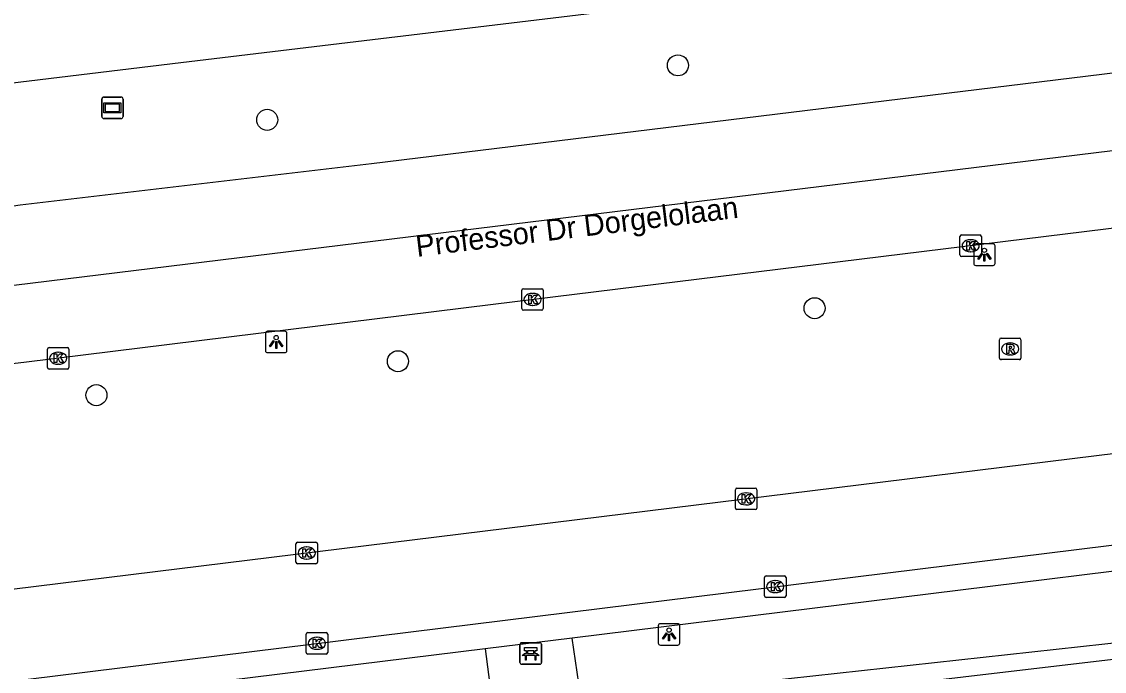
# Model space of a CAD drawing. Extents: x 161477 to 163040, y 383680 to 384868.
# Drawn here: x 162179.5 to 162229.8, y 384039.9 to 384070.2 of the extents above; entities that cross this region are included whole.
import ezdxf

# ---------------------------------------------------------------- set-up
doc = ezdxf.new("R2010")
doc.units = 0
for name, color, linetype in [('IMGEO_Bank', 7, 'Continuous'), ('IMGEO_Boom', 7, 'Continuous'), ('IMGEO_Haag', 7, 'Continuous'), ('IMGEO_Kolk', 7, 'Continuous'), ('IMGEO_Lichtpunt', 7, 'Continuous'), ('IMGEO_Openbare_ruimte_label', 7, 'Continuous'), ('IMGEO_Rijbaan_lokaal_gesloten', 7, 'Continuous'), ('IMGEO_Rioolput', 7, 'Continuous'), ('IMGEO_Verklikker', 7, 'Continuous'), ('IMGEO_Voetpad_open', 7, 'Continuous')]:
    doc.layers.add(name, color=color, linetype=linetype)

msp = doc.modelspace()

# ---------------------------------------------------------------- linework, layer by layer
at = {"layer": 'IMGEO_Bank'}
for p, q in [((162202.681, 384040.354), (162202.681, 384041.195)), ((162202.681, 384041.195), (162202.681, 384040.354)), ((162202.756, 384041.279), (162203.597, 384041.279)), ((162203.597, 384041.279), (162202.756, 384041.279)), ((162203.681, 384041.204), (162203.681, 384040.363)), ((162203.681, 384040.363), (162203.681, 384041.204)), ((162203.378, 384040.677), (162202.985, 384040.677)), ((162202.99, 384040.785), (162202.99, 384040.891)), ((162203.034, 384040.891), (162203.034, 384040.785)), ((162203.322, 384040.897), (162203.04, 384040.897)), ((162203.04, 384040.779), (162203.322, 384040.779)), ((162203.328, 384040.785), (162203.328, 384040.891)), ((162203.372, 384040.891), (162203.372, 384040.785)), ((162203.606, 384040.279), (162202.765, 384040.279)), ((162202.765, 384040.279), (162203.606, 384040.279))]:
    msp.add_line(p, q, dxfattribs=at)
for points in [[(162202.984, 384040.897), (162202.898, 384040.897), (162202.898, 384041.058), (162203.461, 384041.058), (162203.461, 384040.897), (162203.378, 384040.897)], [(162202.928, 384040.677), (162202.786, 384040.677), (162202.898, 384040.779), (162202.984, 384040.779)], [(162202.978, 384040.67), (162202.978, 384040.463), (162202.935, 384040.463), (162202.935, 384040.67)], [(162203.378, 384040.779), (162203.461, 384040.779), (162203.573, 384040.677), (162203.434, 384040.677)], [(162203.428, 384040.67), (162203.428, 384040.463), (162203.384, 384040.463), (162203.384, 384040.67)]]:
    msp.add_lwpolyline(points, dxfattribs=at)
for centre, radius, start, end in [((162202.759, 384041.201), 0.0779, 92.4484, 184.2845), ((162202.759, 384041.201), 0.0779, 92.4484, 184.2845), ((162203.603, 384041.201), 0.0779, 2.4484, 94.2845), ((162203.603, 384041.201), 0.0779, 2.4484, 94.2845), ((162202.928, 384040.67), 0.00671, 2.8957, 87.1043), ((162202.985, 384040.67), 0.00671, 92.8957, 177.1043), ((162202.983, 384040.89), 0.00671, 2.8957, 87.1043), ((162202.983, 384040.786), 0.00671, 272.8957, 357.1043), ((162203.04, 384040.89), 0.00671, 92.8957, 177.1043), ((162203.04, 384040.786), 0.00671, 182.8957, 267.1043), ((162203.322, 384040.89), 0.00671, 2.8957, 87.1043), ((162203.322, 384040.786), 0.00671, 272.8957, 357.1043), ((162203.379, 384040.89), 0.00671, 92.8957, 177.1043), ((162203.379, 384040.786), 0.00671, 182.8957, 267.1043), ((162203.377, 384040.67), 0.00671, 2.8957, 87.1043), ((162203.434, 384040.67), 0.00671, 92.8957, 177.1043), ((162202.759, 384040.357), 0.0779, 182.4484, 274.2845), ((162202.759, 384040.357), 0.0779, 182.4484, 274.2845), ((162203.603, 384040.357), 0.0779, 272.4484, 4.2845), ((162203.603, 384040.357), 0.0779, 272.4484, 4.2845)]:
    msp.add_arc(centre, radius, start, end, dxfattribs=at)
at = {"layer": 'IMGEO_Boom'}
for centre in [(162210.025, 384068.122), (162190.933, 384065.589), (162216.38, 384056.83), (162197.009, 384054.364), (162182.993, 384052.787)]:
    msp.add_circle(centre, 0.489, dxfattribs=at)
at = {"layer": 'IMGEO_Haag'}
for points in [[(162240.057, 384042.327), (162214.028, 384039.472)], [(162219.917, 383995.975), (162220.046, 383995.991), (162214.99, 384038.711), (162240.134, 384041.676)]]:
    msp.add_lwpolyline(points, dxfattribs=at)
at = {"layer": 'IMGEO_Kolk'}
for p, q in [((162223.134, 384059.309), (162223.134, 384060.161)), ((162223.209, 384060.235), (162224.061, 384060.235)), ((162224.135, 384060.161), (162224.135, 384059.309)), ((162223.622, 384060.015), (162223.647, 384060.015)), ((162224.061, 384059.235), (162223.209, 384059.235)), ((162223.645, 384059.455), (162223.62, 384059.455)), ((162202.767, 384056.812), (162202.767, 384057.664)), ((162202.842, 384057.738), (162203.694, 384057.738)), ((162203.768, 384057.664), (162203.768, 384056.812)), ((162203.255, 384057.518), (162203.28, 384057.518)), ((162203.694, 384056.738), (162202.842, 384056.738)), ((162203.278, 384056.958), (162203.253, 384056.958)), ((162180.716, 384054.076), (162180.716, 384054.928)), ((162180.791, 384055.002), (162181.643, 384055.002)), ((162181.204, 384054.782), (162181.229, 384054.782)), ((162181.717, 384054.928), (162181.717, 384054.076)), ((162181.227, 384054.222), (162181.202, 384054.222)), ((162181.643, 384054.002), (162180.791, 384054.002)), ((162212.695, 384047.54), (162212.695, 384048.392)), ((162212.77, 384048.466), (162213.622, 384048.466)), ((162213.183, 384048.246), (162213.208, 384048.246)), ((162213.696, 384048.392), (162213.696, 384047.54)), ((162213.206, 384047.686), (162213.181, 384047.686)), ((162213.622, 384047.466), (162212.77, 384047.466)), ((162192.269, 384045.022), (162192.269, 384045.874)), ((162192.344, 384045.948), (162193.196, 384045.948)), ((162192.757, 384045.728), (162192.782, 384045.728)), ((162193.27, 384045.874), (162193.27, 384045.022)), ((162192.78, 384045.168), (162192.755, 384045.168)), ((162193.196, 384044.948), (162192.344, 384044.948)), ((162214.05, 384043.458), (162214.05, 384044.31)), ((162214.125, 384044.384), (162214.977, 384044.384)), ((162214.538, 384044.164), (162214.563, 384044.164)), ((162215.051, 384044.31), (162215.051, 384043.458)), ((162214.561, 384043.604), (162214.536, 384043.604)), ((162214.977, 384043.384), (162214.125, 384043.384)), ((162192.744, 384040.823), (162192.744, 384041.675)), ((162192.819, 384041.749), (162193.671, 384041.749)), ((162193.232, 384041.529), (162193.257, 384041.529)), ((162193.745, 384041.675), (162193.745, 384040.823)), ((162193.671, 384040.749), (162192.819, 384040.749)), ((162193.255, 384040.969), (162193.23, 384040.969))]:
    msp.add_line(p, q, dxfattribs=at)
for points in [[(162223.134, 384059.309), (162223.134, 384060.161)], [(162223.209, 384060.235), (162224.061, 384060.235)], [(162224.135, 384060.161), (162224.135, 384059.309)], [(162223.455, 384059.935), (162223.578, 384059.935), (162223.578, 384059.784), (162223.708, 384059.935), (162223.872, 384059.935), (162223.726, 384059.784), (162223.879, 384059.535), (162223.727, 384059.535), (162223.642, 384059.699), (162223.578, 384059.632), (162223.578, 384059.535), (162223.455, 384059.535), (162223.455, 384059.935)], [(162224.061, 384059.235), (162223.209, 384059.235)], [(162202.767, 384056.812), (162202.767, 384057.664)], [(162202.842, 384057.738), (162203.694, 384057.738)], [(162203.768, 384057.664), (162203.768, 384056.812)], [(162203.088, 384057.438), (162203.211, 384057.438), (162203.211, 384057.287), (162203.341, 384057.438), (162203.505, 384057.438), (162203.359, 384057.287), (162203.512, 384057.038), (162203.36, 384057.038), (162203.275, 384057.202), (162203.211, 384057.135), (162203.211, 384057.038), (162203.088, 384057.038), (162203.088, 384057.438)], [(162203.694, 384056.738), (162202.842, 384056.738)], [(162180.716, 384054.076), (162180.716, 384054.928)], [(162180.791, 384055.002), (162181.643, 384055.002)], [(162181.037, 384054.702), (162181.16, 384054.702), (162181.16, 384054.551), (162181.29, 384054.702), (162181.454, 384054.702), (162181.308, 384054.551), (162181.461, 384054.302), (162181.309, 384054.302), (162181.224, 384054.466), (162181.16, 384054.399), (162181.16, 384054.302), (162181.037, 384054.302), (162181.037, 384054.702)], [(162181.717, 384054.928), (162181.717, 384054.076)], [(162181.643, 384054.002), (162180.791, 384054.002)], [(162212.695, 384047.54), (162212.695, 384048.392)], [(162212.77, 384048.466), (162213.622, 384048.466)], [(162213.016, 384048.166), (162213.139, 384048.166), (162213.139, 384048.015), (162213.269, 384048.166), (162213.433, 384048.166), (162213.287, 384048.015), (162213.44, 384047.766), (162213.288, 384047.766), (162213.203, 384047.93), (162213.139, 384047.863), (162213.139, 384047.766), (162213.016, 384047.766), (162213.016, 384048.166)], [(162213.696, 384048.392), (162213.696, 384047.54)], [(162213.622, 384047.466), (162212.77, 384047.466)], [(162192.269, 384045.022), (162192.269, 384045.874)], [(162192.344, 384045.948), (162193.196, 384045.948)], [(162192.59, 384045.648), (162192.713, 384045.648), (162192.713, 384045.497), (162192.843, 384045.648), (162193.007, 384045.648), (162192.861, 384045.497), (162193.014, 384045.248), (162192.862, 384045.248), (162192.777, 384045.412), (162192.713, 384045.345), (162192.713, 384045.248), (162192.59, 384045.248), (162192.59, 384045.648)], [(162193.27, 384045.874), (162193.27, 384045.022)], [(162193.196, 384044.948), (162192.344, 384044.948)], [(162214.05, 384043.458), (162214.05, 384044.31)], [(162214.125, 384044.384), (162214.977, 384044.384)], [(162214.371, 384044.084), (162214.494, 384044.084), (162214.494, 384043.933), (162214.624, 384044.084), (162214.788, 384044.084), (162214.642, 384043.933), (162214.795, 384043.684), (162214.643, 384043.684), (162214.558, 384043.848), (162214.494, 384043.781), (162214.494, 384043.684), (162214.371, 384043.684), (162214.371, 384044.084)], [(162215.051, 384044.31), (162215.051, 384043.458)], [(162214.977, 384043.384), (162214.125, 384043.384)], [(162192.744, 384040.823), (162192.744, 384041.675)], [(162192.819, 384041.749), (162193.671, 384041.749)], [(162193.745, 384041.675), (162193.745, 384040.823)], [(162193.065, 384041.449), (162193.188, 384041.449), (162193.188, 384041.298), (162193.318, 384041.449), (162193.482, 384041.449), (162193.336, 384041.298), (162193.489, 384041.049), (162193.337, 384041.049), (162193.252, 384041.213), (162193.188, 384041.146), (162193.188, 384041.049), (162193.065, 384041.049), (162193.065, 384041.449)], [(162193.671, 384040.749), (162192.819, 384040.749)]]:
    msp.add_lwpolyline(points, dxfattribs=at)
for centre, start, end in [((162223.211, 384060.159), 91.552, 178.448), ((162223.211, 384060.159), 91.552, 178.448), ((162224.059, 384060.159), 1.552, 88.448), ((162224.059, 384060.159), 1.552, 88.448), ((162223.211, 384059.311), 181.552, 268.448), ((162223.211, 384059.311), 181.552, 268.448), ((162224.059, 384059.311), 271.552, 358.448), ((162224.059, 384059.311), 271.552, 358.448), ((162202.844, 384057.662), 91.552, 178.448), ((162202.844, 384057.662), 91.552, 178.448), ((162203.692, 384057.662), 1.552, 88.448), ((162203.692, 384057.662), 1.552, 88.448), ((162202.844, 384056.814), 181.552, 268.448), ((162202.844, 384056.814), 181.552, 268.448), ((162203.692, 384056.814), 271.552, 358.448), ((162203.692, 384056.814), 271.552, 358.448), ((162180.793, 384054.926), 91.552, 178.448), ((162180.793, 384054.926), 91.552, 178.448), ((162181.641, 384054.926), 1.552, 88.448), ((162181.641, 384054.926), 1.552, 88.448), ((162180.793, 384054.078), 181.552, 268.448), ((162180.793, 384054.078), 181.552, 268.448), ((162181.641, 384054.078), 271.552, 358.448), ((162181.641, 384054.078), 271.552, 358.448), ((162212.772, 384048.39), 91.552, 178.448), ((162212.772, 384048.39), 91.552, 178.448), ((162213.62, 384048.39), 1.552, 88.448), ((162213.62, 384048.39), 1.552, 88.448), ((162212.772, 384047.542), 181.552, 268.448), ((162212.772, 384047.542), 181.552, 268.448), ((162213.62, 384047.542), 271.552, 358.448), ((162213.62, 384047.542), 271.552, 358.448), ((162192.346, 384045.872), 91.552, 178.448), ((162192.346, 384045.872), 91.552, 178.448), ((162193.194, 384045.872), 1.552, 88.448), ((162193.194, 384045.872), 1.552, 88.448), ((162192.346, 384045.024), 181.552, 268.448), ((162192.346, 384045.024), 181.552, 268.448), ((162193.194, 384045.024), 271.552, 358.448), ((162193.194, 384045.024), 271.552, 358.448), ((162214.127, 384044.308), 91.552, 178.448), ((162214.127, 384044.308), 91.552, 178.448), ((162214.975, 384044.308), 1.552, 88.448), ((162214.975, 384044.308), 1.552, 88.448), ((162214.127, 384043.46), 181.552, 268.448), ((162214.127, 384043.46), 181.552, 268.448), ((162214.975, 384043.46), 271.552, 358.448), ((162214.975, 384043.46), 271.552, 358.448), ((162192.821, 384041.673), 91.552, 178.448), ((162192.821, 384041.673), 91.552, 178.448), ((162193.669, 384041.673), 1.552, 88.448), ((162193.669, 384041.673), 1.552, 88.448), ((162192.821, 384040.825), 181.552, 268.448), ((162192.821, 384040.825), 181.552, 268.448), ((162193.669, 384040.825), 271.552, 358.448), ((162193.669, 384040.825), 271.552, 358.448)]:
    msp.add_arc(centre, 0.0765, start, end, dxfattribs=at)
for centre, major_axis, ratio, start_param, end_param in [((162223.621, 384059.735), (-0.387, 0.002), 0.722429, 4.712389, 7.853982), ((162223.646, 384059.735), (-0.39, 0.002), 0.717154, 1.570796, 4.712389), ((162203.254, 384057.238), (-0.387, 0.002), 0.722429, 4.712389, 7.853982), ((162203.279, 384057.238), (-0.39, 0.002), 0.717154, 1.570796, 4.712389), ((162181.203, 384054.502), (-0.387, 0.002), 0.722429, 4.712389, 7.853982), ((162181.228, 384054.502), (-0.39, 0.002), 0.717154, 1.570796, 4.712389), ((162213.182, 384047.966), (-0.387, 0.002), 0.722429, 4.712389, 7.853982), ((162213.207, 384047.966), (-0.39, 0.002), 0.717154, 1.570796, 4.712389), ((162192.756, 384045.448), (-0.387, 0.002), 0.722429, 4.712389, 7.853982), ((162192.781, 384045.448), (-0.39, 0.002), 0.717154, 1.570796, 4.712389), ((162214.537, 384043.884), (-0.387, 0.002), 0.722429, 4.712389, 7.853982), ((162214.562, 384043.884), (-0.39, 0.002), 0.717154, 1.570796, 4.712389), ((162193.231, 384041.249), (-0.387, 0.002), 0.722429, 4.712389, 7.853982), ((162193.256, 384041.249), (-0.39, 0.002), 0.717154, 1.570796, 4.712389)]:
    msp.add_ellipse(centre, major_axis=major_axis, ratio=ratio, start_param=start_param, end_param=end_param, dxfattribs=at)
at = {"layer": 'IMGEO_Lichtpunt'}
for p, q in [((162223.775, 384059.723), (162223.775, 384058.916)), ((162223.775, 384059.723), (162223.775, 384058.916)), ((162224.677, 384059.818), (162223.869, 384059.818)), ((162224.677, 384059.818), (162223.869, 384059.818)), ((162224.771, 384058.916), (162224.771, 384059.723)), ((162224.771, 384058.916), (162224.771, 384059.723)), ((162223.869, 384058.822), (162224.677, 384058.822)), ((162223.869, 384058.822), (162224.677, 384058.822)), ((162190.851, 384055.667), (162190.851, 384054.86)), ((162190.851, 384055.667), (162190.851, 384054.86)), ((162191.753, 384055.762), (162190.945, 384055.762)), ((162191.753, 384055.762), (162190.945, 384055.762)), ((162191.847, 384054.86), (162191.847, 384055.667)), ((162191.847, 384054.86), (162191.847, 384055.667)), ((162190.945, 384054.766), (162191.753, 384054.766)), ((162190.945, 384054.766), (162191.753, 384054.766)), ((162209.115, 384042.066), (162209.115, 384041.259)), ((162209.115, 384042.066), (162209.115, 384041.259)), ((162210.017, 384042.161), (162209.209, 384042.161)), ((162210.017, 384042.161), (162209.209, 384042.161)), ((162210.111, 384041.259), (162210.111, 384042.066)), ((162210.111, 384041.259), (162210.111, 384042.066)), ((162209.209, 384041.165), (162210.017, 384041.165)), ((162209.209, 384041.165), (162210.017, 384041.165))]:
    msp.add_line(p, q, dxfattribs=at)
for points in [[(162224.149, 384059.387), (162224.188, 384059.359), (162224, 384059.097), (162223.962, 384059.124), (162224.149, 384059.387)], [(162224.251, 384059.339), (162224.298, 384059.339), (162224.298, 384059.017), (162224.251, 384059.017), (162224.251, 384059.339)], [(162224.361, 384059.359), (162224.399, 384059.386), (162224.586, 384059.124), (162224.547, 384059.096), (162224.361, 384059.359)], [(162191.225, 384055.331), (162191.264, 384055.303), (162191.076, 384055.041), (162191.038, 384055.068), (162191.225, 384055.331)], [(162191.327, 384055.283), (162191.374, 384055.283), (162191.374, 384054.961), (162191.327, 384054.961), (162191.327, 384055.283)], [(162191.437, 384055.303), (162191.475, 384055.33), (162191.662, 384055.068), (162191.623, 384055.04), (162191.437, 384055.303)], [(162209.489, 384041.73), (162209.528, 384041.702), (162209.34, 384041.44), (162209.302, 384041.467), (162209.489, 384041.73)], [(162209.591, 384041.682), (162209.638, 384041.682), (162209.638, 384041.36), (162209.591, 384041.36), (162209.591, 384041.682)], [(162209.701, 384041.702), (162209.739, 384041.729), (162209.926, 384041.467), (162209.887, 384041.439), (162209.701, 384041.702)]]:
    msp.add_lwpolyline(points, dxfattribs=at)
for centre in [(162224.274, 384059.521), (162191.35, 384055.465), (162209.614, 384041.864)]:
    msp.add_circle(centre, 0.0994, dxfattribs=at)
for centre, start, end in [((162223.869, 384059.723), 90, 180), ((162223.869, 384059.723), 90, 180), ((162224.677, 384059.723), 0, 90), ((162224.677, 384059.723), 0, 90), ((162223.869, 384058.916), 180, 270), ((162223.869, 384058.916), 180, 270), ((162224.677, 384058.916), 270, 0), ((162224.677, 384058.916), 270, 360), ((162190.945, 384055.667), 90, 180), ((162190.945, 384055.667), 90, 180), ((162191.753, 384055.667), 0, 90), ((162191.753, 384055.667), 0, 90), ((162190.945, 384054.86), 180, 270), ((162190.945, 384054.86), 180, 270), ((162191.753, 384054.86), 270, 0), ((162191.753, 384054.86), 270, 360), ((162209.209, 384042.066), 90, 180), ((162209.209, 384042.066), 90, 180), ((162210.017, 384042.066), 0, 90), ((162210.017, 384042.066), 0, 90), ((162209.209, 384041.259), 180, 270), ((162209.209, 384041.259), 180, 270), ((162210.017, 384041.259), 270, 0), ((162210.017, 384041.259), 270, 360)]:
    msp.add_arc(centre, 0.0946, start, end, dxfattribs=at)
at = {"layer": 'IMGEO_Rijbaan_lokaal_gesloten'}
for points in [[(162005.779, 384046.356), (162186.915, 384068.26), (162246.983, 384075.474)], [(162247.846, 384069.907), (162195.789, 384063.545), (162179.444, 384061.624), (162173.495, 384060.723), (162097.498, 384051.298), (162006.847, 384040.554)], [(161696.618, 383999.076), (161717.081, 384001.544), (161768.879, 384007.897), (161825.477, 384014.75), (161917.35, 384025.954), (162007.495, 384037.033), (162008.923, 384037.209), (162102.422, 384048.613), (162177.172, 384057.667), (162248.391, 384066.39)], [(162248.941, 384062.845), (162201.441, 384057.009), (162179.625, 384054.308), (162139.298, 384049.588), (162134.982, 384048.963), (162131.051, 384048.617), (162073.42, 384041.498), (162051.67, 384038.989), (162036.516, 384037.016), (162009.54, 384033.893)], [(162234.886, 384050.639), (161987.776, 384020.184)], [(162136.714, 384034.256), (162236.067, 384046.546)]]:
    msp.add_lwpolyline(points, dxfattribs=at)
at = {"layer": 'IMGEO_Rioolput'}
for p, q in [((162224.971, 384054.512), (162224.971, 384055.364)), ((162225.046, 384055.438), (162225.898, 384055.438)), ((162225.459, 384055.218), (162225.484, 384055.218)), ((162225.972, 384055.364), (162225.972, 384054.512)), ((162225.482, 384054.658), (162225.457, 384054.658)), ((162225.898, 384054.438), (162225.046, 384054.438))]:
    msp.add_line(p, q, dxfattribs=at)
for points in [[(162224.971, 384054.512), (162224.971, 384055.364)], [(162225.046, 384055.438), (162225.898, 384055.438)], [(162225.56, 384055.136), (162225.308, 384055.138), (162225.308, 384054.738)], [(162225.972, 384055.364), (162225.972, 384054.512)], [(162225.308, 384054.738), (162225.432, 384054.738), (162225.432, 384054.9), (162225.443, 384054.9)], [(162225.486, 384055.057), (162225.432, 384055.057), (162225.432, 384054.976)], [(162225.432, 384054.976), (162225.484, 384054.976)], [(162225.49, 384054.871), (162225.561, 384054.738), (162225.701, 384054.738), (162225.636, 384054.864)], [(162225.898, 384054.438), (162225.046, 384054.438)]]:
    msp.add_lwpolyline(points, dxfattribs=at)
for centre, radius, start, end in [((162225.048, 384055.362), 0.0765, 91.552, 178.448), ((162225.048, 384055.362), 0.0765, 91.552, 178.448), ((162225.559, 384055.026), 0.109, 350.3612, 89.416), ((162225.896, 384055.362), 0.0765, 1.552, 88.448), ((162225.896, 384055.362), 0.0765, 1.552, 88.448), ((162225.442, 384054.847), 0.0533, 26.0293, 88.6989), ((162225.468, 384055.165), 0.19, 274.7715, 282.9687), ((162225.492, 384054.961), 0.0964, 77.0061, 93.1865), ((162225.506, 384055.018), 0.0378, 276.6634, 79.6772), ((162225.557, 384055.026), 0.112, 277.5842, 350.9817), ((162225.541, 384054.811), 0.108, 29.5134, 73.7905), ((162225.048, 384054.514), 0.0765, 181.552, 268.448), ((162225.048, 384054.514), 0.0765, 181.552, 268.448), ((162225.896, 384054.514), 0.0765, 271.552, 358.448), ((162225.896, 384054.514), 0.0765, 271.552, 358.448)]:
    msp.add_arc(centre, radius, start, end, dxfattribs=at)
for centre, major_axis, ratio, start_param, end_param in [((162225.458, 384054.938), (-0.387, 0.002), 0.722429, 4.712389, 7.853982), ((162225.483, 384054.938), (-0.39, 0.002), 0.717154, 1.570796, 4.712389)]:
    msp.add_ellipse(centre, major_axis=major_axis, ratio=ratio, start_param=start_param, end_param=end_param, dxfattribs=at)
at = {"layer": 'IMGEO_Verklikker'}
for p, q in [((162183.24, 384065.75), (162183.24, 384066.55)), ((162183.24, 384066.55), (162183.24, 384065.75)), ((162183.34, 384066.65), (162184.13, 384066.65)), ((162184.13, 384066.65), (162183.34, 384066.65)), ((162184.23, 384066.55), (162184.23, 384065.75)), ((162184.23, 384065.75), (162184.23, 384066.55)), ((162184.13, 384065.65), (162183.34, 384065.65)), ((162183.34, 384065.65), (162184.13, 384065.65))]:
    msp.add_line(p, q, dxfattribs=at)
for points in [[(162183.341, 384066.382), (162184.129, 384066.382), (162184.129, 384065.918), (162183.341, 384065.918), (162183.341, 384066.382)], [(162183.406, 384066.317), (162183.406, 384065.983), (162184.064, 384065.983), (162184.064, 384066.317), (162183.406, 384066.317)]]:
    msp.add_lwpolyline(points, dxfattribs=at)
for centre, start, end in [((162183.34, 384066.55), 90, 180), ((162183.34, 384066.55), 90, 180), ((162184.13, 384066.55), 0, 90), ((162184.13, 384066.55), 360, 90), ((162183.34, 384065.75), 180, 270), ((162183.34, 384065.75), 180, 270), ((162184.13, 384065.75), 270, 0), ((162184.13, 384065.75), 270, 0)]:
    msp.add_arc(centre, 0.1, start, end, dxfattribs=at)
at = {"layer": 'IMGEO_Voetpad_open'}
for points in [[(162235.705, 384045.271), (162205.117, 384041.494)], [(162205.117, 384041.494), (162201.07, 384040.995)], [(162201.07, 384040.995), (162201.323, 384038.96), (162205.419, 384039.381), (162205.117, 384041.494)], [(162201.07, 384040.995), (162166.269, 384036.698)]]:
    msp.add_lwpolyline(points, dxfattribs=at)

# ---------------------------------------------------------------- texts
at = {"layer": 'IMGEO_Openbare_ruimte_label'}
msp.add_text('Professor Dr Dorgelolaan', height=1, rotation=6.9474, dxfattribs=at).set_placement((162197.899, 384059.215))

doc.saveas('drawing.dxf')
